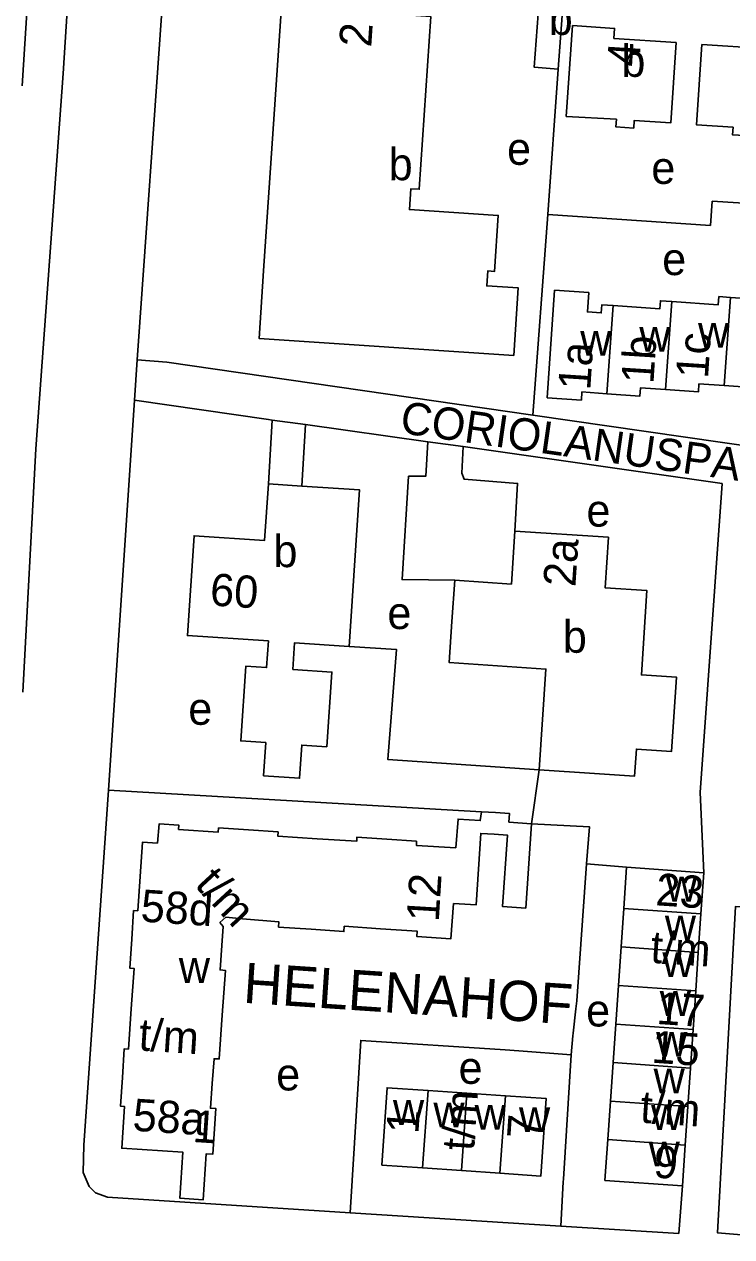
# Model space of a CAD drawing. Extents: x 161773 to 163836, y 384796 to 386521.
# Drawn here: x 162037.7 to 162125.5, y 385996.4 to 386146.9 of the extents above; entities that cross this region are included whole.
import ezdxf

# ---------------------------------------------------------------- set-up
doc = ezdxf.new("R2010")
doc.units = 0
for name, color, linetype in [('BLT_Basislijn', 7, 'Continuous'), ('BLT_Bebouwing', 7, 'Continuous'), ('BLT_Centroide', 7, 'Continuous'), ('BLT_Huisnummer', 7, 'Continuous'), ('BLT_Huisnummer_reeks', 7, 'Continuous'), ('BLT_Onderverdeling_panden', 7, 'Continuous'), ('BLT_Straatnaam', 7, 'Continuous'), ('BLT_Straatnaam_verkleind', 7, 'Continuous')]:
    doc.layers.add(name, color=color, linetype=linetype)

msp = doc.modelspace()

# ---------------------------------------------------------------- linework, layer by layer
at = {"layer": 'BLT_Basislijn'}
for p, q in [((162055.22, 386154.83), (162051.7, 386105.26)), ((162039.14, 386094.22), (162042.54, 386140.82)), ((162103.97, 386141.37), (162102.65, 386123.34)), ((162122.86, 386121.96), (162123.07, 386124.99)), ((162123.07, 386124.99), (162133.44, 386124.28)), ((162102.65, 386123.34), (162100.82, 386098.4)), ((162102.65, 386123.34), (162122.86, 386121.96)), ((162051.37, 386100.29), (162051.7, 386105.26)), ((162051.37, 386100.29), (162048.13, 386051.86)), ((162100.82, 386098.4), (162131.45, 386093.97)), ((162068.44, 386097.81), (162067.99, 386089.89)), ((162068.44, 386097.81), (162072.6, 386097.26)), ((162072.16, 386089.61), (162072.6, 386097.26)), ((162072.6, 386097.26), (162087.79, 386095.12)), ((162092.17, 386094.51), (162087.79, 386095.12)), ((162100.62, 386047.7), (162101.59, 386054.4)), ((162048.13, 386051.86), (162094.42, 386049.19)), ((162112.43, 386042.29), (162107.47, 386042.72)), ((162105.81, 386021.7), (162106.15, 386024.72)), ((162105.55, 386019), (162099.05, 386019.49)), ((162104.61, 386003.57), (162105.55, 386019)), ((162118.92, 385996.82), (162119.37, 386002.75)), ((162078.12, 385999.4), (162104.26, 385997.76)), ((162118.92, 385996.82), (162104.26, 385997.76))]:
    msp.add_line(p, q, dxfattribs=at)
for points in [[(162042.87, 386230.52), (162042.34, 386216.4), (162039.17, 386166.67), (162037.43, 386139.3)], [(162047.33, 386216.15), (162042.54, 386140.82)], [(162051.7, 386105.26), (162055.38, 386104.98), (162100.82, 386098.4)], [(162051.37, 386100.29), (162068, 386097.87), (162068.44, 386097.81)], [(162091.11, 386077.91), (162084.59, 386078.01), (162085.39, 386090.82), (162087.54, 386090.85), (162087.79, 386095.12)], [(162039.14, 386094.22), (162037.53, 386064.03)], [(162098.59, 386084.03), (162098.91, 386089.94), (162092.28, 386090.46), (162092.01, 386091.23), (162092.17, 386094.51)], [(162092.17, 386094.51), (162124.28, 386089.93)], [(162124.28, 386089.93), (162121.58, 386051.56), (162122.01, 386041.61)], [(162078, 386069.71), (162083.89, 386069.31), (162082.82, 386055.66), (162101.59, 386054.4)], [(162045.76, 386002.65), (162045.01, 386004.39), (162045.09, 386007.81), (162048.13, 386051.86)], [(162100.62, 386047.7), (162107.85, 386047.29), (162107.47, 386042.72)], [(162106.15, 386024.72), (162106.26, 386025.71), (162107.47, 386042.72)], [(162123.73, 385996.9), (162125.94, 386037.42), (162133.7, 386036.9), (162125.94, 386037.42), (162123.73, 385996.9), (162129.65, 385996.43)], [(162105.55, 386019), (162105.77, 386021.35), (162105.81, 386021.7)], [(162099.05, 386019.49), (162097.38, 386019.61), (162079.45, 386020.79), (162078.12, 385999.4)], [(162104.61, 386003.57), (162104.59, 386003.23), (162104.26, 385997.76)], [(162078.12, 385999.4), (162048.01, 386001.33), (162046.54, 386001.89), (162045.76, 386002.65)]]:
    msp.add_lwpolyline(points, dxfattribs=at)
at = {"layer": 'BLT_Bebouwing'}
for p, q in [((162104.58, 386149.66), (162103.97, 386141.37)), ((162067.99, 386089.89), (162072.16, 386089.61)), ((162094.42, 386049.19), (162096.16, 386049.08)), ((162100.62, 386047.7), (162099.95, 386037.22)), ((162112.43, 386042.29), (162112.08, 386037.19)), ((162122.01, 386041.61), (162121.66, 386036.51)), ((162112.08, 386037.19), (162111.75, 386032.41)), ((162121.66, 386036.51), (162121.34, 386031.73)), ((162111.75, 386032.41), (162111.42, 386027.63)), ((162121.34, 386031.73), (162121.02, 386026.95)), ((162111.42, 386027.63), (162111.09, 386022.83)), ((162121.02, 386026.95), (162120.69, 386022.15)), ((162110.77, 386018.04), (162111.09, 386022.83)), ((162120.36, 386017.35), (162120.69, 386022.15)), ((162110.44, 386013.27), (162110.77, 386018.04)), ((162120.04, 386012.58), (162120.36, 386017.35)), ((162092.61, 386014.24), (162087.81, 386014.57)), ((162097.41, 386013.92), (162092.61, 386014.24)), ((162110.44, 386013.27), (162110.11, 386008.5)), ((162119.71, 386007.81), (162120.04, 386012.58)), ((162110.11, 386008.5), (162109.76, 386003.42)), ((162119.37, 386002.75), (162119.71, 386007.81)), ((162091.94, 386004.64), (162087.13, 386004.97)), ((162096.73, 386004.31), (162091.94, 386004.64)), ((162109.76, 386003.42), (162119.37, 386002.75))]:
    msp.add_line(p, q, dxfattribs=at)
for points in [[(162098.44, 386105.83), (162066.84, 386107.94), (162067.4, 386116.31), (162069.63, 386149.16), (162088.15, 386147.92)], [(162103.97, 386141.37), (162100.99, 386141.59), (162101.6, 386149.88)], [(162088.15, 386147.92), (162086.71, 386126.45), (162085.67, 386126.52), (162085.5, 386123.94), (162096.52, 386123.2), (162096.06, 386116.26), (162095.21, 386116.32), (162095.09, 386114.46), (162099, 386114.2), (162098.44, 386105.83)], [(162105.71, 386146.78), (162110.95, 386146.43), (162110.87, 386145.18), (162118.59, 386144.66), (162117.92, 386134.69), (162113.4, 386134.99), (162113.33, 386134.05), (162111.1, 386134.21), (162111.17, 386135.14), (162104.95, 386135.5), (162105.71, 386146.78)], [(162121.79, 386144.44), (162129.51, 386143.92), (162129.6, 386145.16), (162134.84, 386144.81)], [(162134.08, 386133.53), (162127.88, 386134.01), (162127.81, 386133.08), (162125.58, 386133.23), (162125.65, 386134.16), (162121.11, 386134.47), (162121.79, 386144.44)], [(162110.77, 386112.01), (162109.37, 386112.11), (162109.3, 386111.1), (162107.58, 386111.22), (162107.75, 386113.62), (162103.51, 386113.91), (162102.59, 386100.57)], [(162125.34, 386113.03), (162123.89, 386113.13), (162123.82, 386112.12), (162118.06, 386112.52)], [(162132.7, 386113.53), (162131.14, 386113.64), (162131.07, 386112.63), (162125.34, 386113.03)], [(162118.06, 386112.52), (162116.63, 386112.62), (162116.56, 386111.61), (162110.77, 386112.01)], [(162124.53, 386102.09), (162128.6, 386101.8), (162128.67, 386102.81), (162131.95, 386102.6)], [(162102.59, 386100.57), (162106.83, 386100.28), (162106.9, 386101.29), (162109.97, 386101.07)], [(162109.97, 386101.07), (162114.09, 386100.79), (162114.16, 386101.8), (162117.26, 386101.58)], [(162117.26, 386101.58), (162121.35, 386101.3), (162121.42, 386102.3), (162124.53, 386102.09)], [(162078, 386069.71), (162071.25, 386070.17), (162071.03, 386066.86), (162075.87, 386066.53), (162075.24, 386057.25), (162072.14, 386057.46), (162071.86, 386053.35), (162067.4, 386053.65), (162067.67, 386057.76), (162064.57, 386057.97), (162065.19, 386067.25), (162067.77, 386067.08), (162067.99, 386070.38), (162057.94, 386071.06), (162058.77, 386083.45), (162067.51, 386082.86), (162067.99, 386089.89)], [(162072.16, 386089.61), (162079.31, 386089.13), (162078.97, 386084.14), (162078, 386069.71)], [(162091.11, 386077.91), (162098.15, 386077.44), (162098.59, 386084.03)], [(162098.59, 386084.03), (162110.19, 386083.26), (162109.77, 386076.99), (162114.97, 386076.64), (162114.27, 386066.17), (162118.64, 386065.87), (162118.03, 386056.67), (162113.66, 386056.96), (162113.44, 386053.61), (162108.45, 386053.95), (162101.59, 386054.4)], [(162101.59, 386054.4), (162102.42, 386066.9), (162090.43, 386067.7), (162090.77, 386072.8), (162091.11, 386077.91)], [(162091.26, 386044.72), (162091.54, 386048.28), (162094.29, 386048.08), (162094.42, 386049.19)], [(162096.16, 386049.08), (162097.9, 386048.97), (162097.83, 386047.9), (162100.62, 386047.7)], [(162054.23, 386045.29), (162054.42, 386047.68), (162056.89, 386047.51), (162056.85, 386046.99), (162061.77, 386046.66), (162061.82, 386047.18), (162065.51, 386046.93)], [(162065.51, 386046.93), (162069.2, 386046.68), (162069.15, 386046.16), (162074.05, 386045.84)], [(162051.03, 386033.35), (162051.27, 386036.92), (162051.78, 386036.89), (162052.39, 386045.42), (162054.23, 386045.29)], [(162074.05, 386045.84), (162078.95, 386045.52), (162078.98, 386046.03), (162082.67, 386045.78)], [(162082.67, 386045.78), (162086.36, 386045.53), (162086.35, 386045), (162091.26, 386044.72)], [(162095.99, 386046.39), (162094.34, 386046.49), (162093.76, 386037.61), (162090.98, 386037.8)], [(162099.95, 386037.22), (162097.06, 386037.41), (162097.65, 386046.28), (162095.99, 386046.39)], [(162122.01, 386041.61), (162112.43, 386042.29)], [(162090.98, 386037.8), (162090.64, 386033.41), (162086.42, 386033.69), (162086.46, 386034.35), (162081.91, 386034.65)], [(162064.76, 386035.91), (162062.73, 386036.09), (162061.95, 386035.42)], [(162061.95, 386035.42), (162062.36, 386034.93), (162062.2, 386032.6)], [(162073.31, 386034.59), (162069.26, 386034.87), (162069.3, 386035.51), (162064.76, 386035.91)], [(162081.91, 386034.65), (162077.41, 386034.96), (162077.37, 386034.3), (162073.31, 386034.59)], [(162050.97, 386024.73), (162051.33, 386029.73), (162050.79, 386029.78), (162051.03, 386033.35)], [(162062.2, 386032.6), (162062, 386029.55), (162062.65, 386029.49), (162062.27, 386023.93)], [(162049.87, 386016.2), (162050.11, 386019.77), (162050.62, 386019.73), (162050.97, 386024.73)], [(162062.27, 386023.93), (162061.89, 386018.5), (162061.26, 386018.52), (162061.03, 386015.44)], [(162061.03, 386015.44), (162060.8, 386012.38), (162061.47, 386012.34), (162061.08, 386006.67), (162060.27, 386006.72), (162059.9, 386001.02), (162057.01, 386001.21), (162057.38, 386006.91), (162049.8, 386007.41), (162050.14, 386012.59), (162049.63, 386012.64), (162049.87, 386016.2)], [(162087.13, 386004.97), (162082.07, 386005.32), (162082.73, 386014.92), (162087.81, 386014.57)], [(162097.41, 386013.92), (162102.48, 386013.58), (162101.8, 386003.96), (162096.73, 386004.31)]]:
    msp.add_lwpolyline(points, dxfattribs=at)
at = {"layer": 'BLT_Onderverdeling_panden'}
for p, q in [((162125.34, 386113.03), (162124.53, 386102.09)), ((162110.77, 386112.01), (162109.97, 386101.07)), ((162118.06, 386112.52), (162117.26, 386101.58)), ((162112.08, 386037.19), (162121.66, 386036.51)), ((162111.75, 386032.41), (162121.34, 386031.73)), ((162111.42, 386027.63), (162121.02, 386026.95)), ((162110.77, 386018.04), (162120.36, 386017.35)), ((162087.13, 386004.97), (162087.81, 386014.57)), ((162091.94, 386004.64), (162092.61, 386014.24)), ((162096.73, 386004.31), (162097.41, 386013.92)), ((162110.44, 386013.27), (162120.04, 386012.58)), ((162110.11, 386008.5), (162119.71, 386007.81))]:
    msp.add_line(p, q, dxfattribs=at)
msp.add_lwpolyline([(162111.09, 386022.83), (162120.69, 386022.15)], dxfattribs=at)

# ---------------------------------------------------------------- texts
at = {"layer": 'BLT_Centroide'}
for s, p in [('b', (162102.78, 386145.62)), ('b', (162111.8, 386140.41)), ('e', (162097.61, 386129.49)), ('b', (162082.92, 386127.58)), ('e', (162115.51, 386127.12)), ('e', (162116.86, 386115.8)), ('w', (162106.69, 386105.78)), ('w', (162114.02, 386106.28)), ('w', (162121.3, 386106.8)), ('e', (162107.46, 386084.58)), ('b', (162068.62, 386079.55)), ('e', (162082.76, 386071.86)), ('b', (162104.53, 386068.92)), ('e', (162058.05, 386059.98)), ('w', (162117.34, 386038.04)), ('w', (162117.19, 386033.23)), ('w', (162116.88, 386028.68)), ('w', (162056.88, 386027.94)), ('e', (162107.42, 386022.53)), ('w', (162116.56, 386023.84)), ('w', (162116.1, 386018.78)), ('e', (162091.59, 386015.41)), ('e', (162068.96, 386014.59)), ('w', (162115.79, 386014.22)), ('w', (162083.45, 386010.31)), ('w', (162088.47, 386010)), ('w', (162093.58, 386009.72)), ('w', (162099.09, 386009.41)), ('w', (162115.49, 386009.69)), ('w', (162115.18, 386005.16))]:
    msp.add_text(s, height=4, dxfattribs=at).set_placement(p)
at = {"layer": 'BLT_Huisnummer'}
for s, rotation, p in [('2', 86.1813, (162080.75, 386144.02)), ('4', 86.3126, (162114.01, 386141.59)), ('1c', 86.3148, (162122.54, 386102.89)), ('1a', 86.3148, (162107.93, 386101.44)), ('1b', 86.3148, (162115.77, 386102.24)), ('2a', 86.1787, (162106.08, 386077.03)), ('60', 356.1428, (162060.66, 386074.81))]:
    msp.add_text(s, height=4, rotation=rotation, dxfattribs=at).set_placement(p)
at = {"layer": 'BLT_Huisnummer_reeks'}
for s, rotation, p in [('t/m', 312.7585, (162058.73, 386040.04)), ('12', 86.5139, (162089.13, 386035.46)), ('23', 356.1356, (162115.96, 386037.58)), ('58d', 356.2503, (162052.07, 386035.56)), ('t/m', 356.1356, (162115.33, 386030.45)), ('17', 356.1356, (162116.07, 386022.85)), ('t/m', 356.2503, (162051.82, 386019.57)), ('15', 356.1356, (162115.46, 386018.04)), ('t/m', 86.1356, (162093.5, 386007.03)), ('t/m', 356.1356, (162114.05, 386010.6)), ('58a', 356.2503, (162051.07, 386009.6)), ('1', 356.2503, (162058.52, 386008.2)), ('1', 86.1356, (162086.6, 386009.13)), ('7', 86.1356, (162101.58, 386008.48)), ('9', 356.1356, (162115.7, 386003.79))]:
    msp.add_text(s, height=4, rotation=rotation, dxfattribs=at).set_placement(p)
at = {"layer": 'BLT_Straatnaam'}
msp.add_text('HELENAHOF', height=5, rotation=356.1892, dxfattribs=at).set_placement((162064.78, 386025.48))
at = {"layer": 'BLT_Straatnaam_verkleind'}
msp.add_text('CORIOLANUSPAD', height=4, rotation=351.9429, dxfattribs=at).set_placement((162084.21, 386096.21))

doc.saveas('drawing.dxf')
